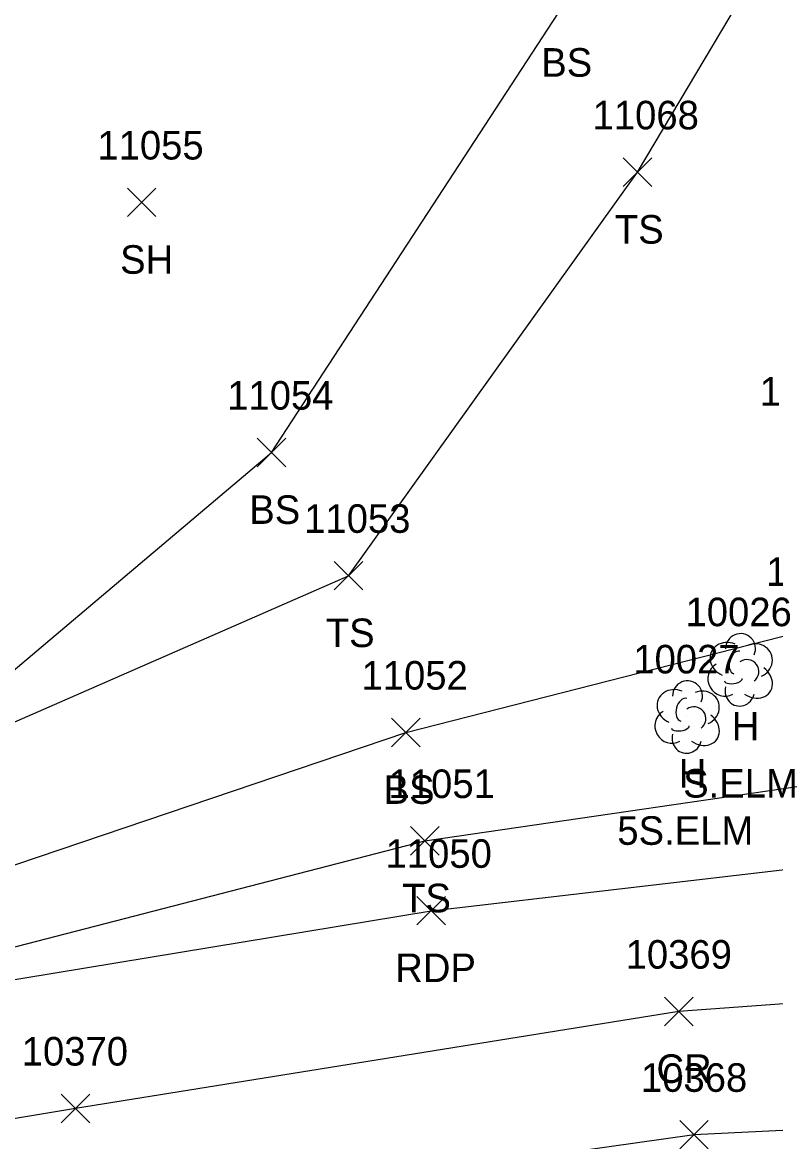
# Model space of a CAD drawing. Extents: x 1475671 to 1477951, y 592661 to 593821.
# Drawn here: x 1476688.2 to 1476740.9, y 593075.6 to 593153.9 of the extents above; entities that cross this region are included whole.
import ezdxf

# ---------------------------------------------------------------- set-up
doc = ezdxf.new("R2010")
doc.units = 0
for name, color, linetype in [('L_A', 7, 'Continuous'), ('L_C', 7, 'Continuous'), ('L_I', 7, 'Continuous'), ('L_TIC', 7, 'Continuous'), ('LELB', 7, 'Continuous'), ('LTD', 7, 'Continuous'), ('P_A', 7, 'Continuous'), ('P_I', 7, 'Continuous'), ('P_TIC', 7, 'Continuous'), ('PET', 7, 'Continuous'), ('PRC', 7, 'Continuous')]:
    doc.layers.add(name, color=color, linetype=linetype)

msp = doc.modelspace()

# ---------------------------------------------------------------- linework, layer by layer
at = {"layer": 'L_TIC'}
for points in [[(1476730.223, 593142.421), (1476732.223, 593144.421)], [(1476732.223, 593142.421), (1476730.223, 593144.421)], [(1476695.532, 593140.311), (1476697.532, 593142.311)], [(1476697.532, 593140.311), (1476695.532, 593142.311)], [(1476704.615, 593122.798), (1476706.615, 593124.798)], [(1476706.615, 593122.798), (1476704.615, 593124.798)], [(1476710.001, 593114.173), (1476712.001, 593116.173)], [(1476712.001, 593114.173), (1476710.001, 593116.173)], [(1476714.012, 593103.198), (1476716.012, 593105.198)], [(1476716.012, 593103.198), (1476714.012, 593105.198)], [(1476715.338, 593095.606), (1476717.338, 593097.606)], [(1476717.338, 593095.606), (1476715.338, 593097.606)]]:
    msp.add_lwpolyline(points, dxfattribs=at)
at = {"layer": 'LELB'}
for points in [[(1476656.284, 593095.976), (1476668.799, 593096.978), (1476674.422, 593093.252), (1476681.706, 593092.914), (1476715.012, 593104.198), (1476743.407, 593111.461), (1476771.495, 593107.276), (1476782.768, 593105.348), (1476795.281, 593099.965), (1476811.259, 593100.054), (1476809.565, 593119.113), (1476813.359, 593153.775), (1476804.907, 593159.056), (1476804.556, 593163.805), (1476803.63, 593168.615), (1476810.963, 593186.977), (1476819.408, 593209.797), (1476828.138, 593245.308), (1476843.633, 593278.61), (1476845.713, 593295.921), (1476849.309, 593306.853)], [(1476678.643, 593100.996), (1476705.615, 593123.798), (1476726.041, 593155.108), (1476737.723, 593186.361), (1476761.68, 593213.282), (1476787.873, 593223.87), (1476810.461, 593252.94), (1476833.913, 593283.757), (1476845.713, 593295.921)], [(1476678.643, 593100.996), (1476711.001, 593115.173), (1476731.223, 593143.421), (1476747.615, 593171.009), (1476767.456, 593198.639), (1476796.546, 593210.231), (1476815.094, 593241.804), (1476843.633, 593278.61)], [(1476564.119, 593090.41), (1476564.346, 593083.027), (1476564.937, 593076.683), (1476605.53, 593077.889), (1476635.384, 593080.856), (1476648.642, 593080.648), (1476656.704, 593082.361), (1476660.671, 593090.953), (1476671.661, 593086.365), (1476683.751, 593088.182), (1476716.338, 593096.606), (1476747.988, 593101.226)]]:
    msp.add_lwpolyline(points, dxfattribs=at)
at = {"layer": 'LTD'}
for p, q in [((1476738.38, 593108.636), (1476738.38, 593108.636)), ((1476738.38, 593108.636), (1476738.38, 593108.636)), ((1476734.671, 593105.33), (1476734.671, 593105.33)), ((1476734.671, 593105.33), (1476734.671, 593105.33))]:
    msp.add_line(p, q, dxfattribs=at)
for centre in [(1476738.427, 593110.07), (1476734.717, 593106.764)]:
    msp.add_arc(centre, 1.047, 335.52715, 180.95627, dxfattribs=at)
for centre, major_axis, ratio, start_param, end_param in [((1476737.588, 593109.302), (1.21, -0.512), 0.895232, 1.570796, 4.712389), ((1476739.422, 593109.219), (-1.141, -0.483), 0.949671, 1.570796, 4.712389), ((1476738.172, 593109.094), (-0.208, -0.792), 0.645439, 3.141593, 6.283185), ((1476737.297, 593107.927), (0.584, -1.042), 0.959034, 3.141593, 6.283185), ((1476738.88, 593108.469), (-0.5, 0.667), 0.989748, 3.141593, 6.283185), ((1476739.38, 593107.803), (-1.09, 0.792), 0.841452, 1.570796, 4.712389), ((1476733.879, 593105.997), (1.21, -0.512), 0.895232, 1.570796, 4.712389), ((1476738.38, 593107.136), (0.265, 1.061), 0.942809, 1.570796, 4.712389), ((1476737.922, 593107.886), (-0.625, -0.083), 0.423636, 0, 3.141593), ((1476734.462, 593105.788), (-0.208, -0.792), 0.645439, 3.141593, 6.283185), ((1476735.712, 593105.914), (-1.141, -0.483), 0.949671, 1.570796, 4.712389), ((1476735.171, 593105.164), (-0.5, 0.667), 0.989748, 3.141593, 6.283185), ((1476733.587, 593104.622), (0.584, -1.042), 0.959034, 3.141593, 6.283185), ((1476735.671, 593104.497), (-1.09, 0.792), 0.841452, 1.570796, 4.712389), ((1476734.212, 593104.58), (-0.625, -0.083), 0.423636, 0, 3.141593), ((1476734.671, 593103.83), (0.265, 1.061), 0.942809, 1.570796, 4.712389)]:
    msp.add_ellipse(centre, major_axis=major_axis, ratio=ratio, start_param=start_param, end_param=end_param, dxfattribs=at)
at = {"layer": 'P_TIC'}
for points in [[(1476715.781, 593090.72), (1476717.781, 593092.72)], [(1476717.781, 593090.72), (1476715.781, 593092.72)], [(1476733.111, 593083.661), (1476735.111, 593085.661)], [(1476735.111, 593083.661), (1476733.111, 593085.661)], [(1476690.896, 593076.875), (1476692.896, 593078.875)], [(1476692.896, 593076.875), (1476690.896, 593078.875)], [(1476734.172, 593075.036), (1476736.172, 593077.036)], [(1476736.172, 593075.036), (1476734.172, 593077.036)]]:
    msp.add_lwpolyline(points, dxfattribs=at)
at = {"layer": 'PET'}
for points in [[(1476550.122, 593088.216), (1476546.989, 593080.789), (1476546.616, 593074.303), (1476558.015, 593070.453), (1476566.603, 593070.835), (1476605.696, 593074.016), (1476651.648, 593078.887), (1476683.811, 593086.28), (1476716.781, 593091.72), (1476756.304, 593096.319), (1476786.758, 593094.615), (1476795.521, 593092.664), (1476816.876, 593085.292), (1476835.432, 593074.221), (1476828.621, 593102.019), (1476824.417, 593119.747), (1476821.585, 593140.768), (1476821.023, 593163.56), (1476821.925, 593180.441), (1476827.117, 593207.843), (1476837.471, 593243.387), (1476848.828, 593278.298), (1476858.441, 593303.191), (1476868.192, 593333.861)], [(1476876.688, 592931.371), (1476866.386, 592975.941), (1476855.424, 593012.866), (1476851.348, 593023.14), (1476844.626, 593035.784), (1476834.266, 593048.701), (1476823.419, 593058.993), (1476807.599, 593067.923), (1476802.866, 593070.053), (1476785.813, 593074.828), (1476762.309, 593077.345), (1476735.172, 593076.036), (1476692.749, 593070.032), (1476654.269, 593063.281), (1476593.38, 593051.399), (1476557.145, 593047.344), (1476521.335, 593044.375), (1476462.498, 593038.202)]]:
    msp.add_lwpolyline(points, dxfattribs=at)
at = {"layer": 'PRC'}
msp.add_lwpolyline([(1476783.703, 593084.944), (1476761.584, 593086.675), (1476734.111, 593084.661), (1476691.896, 593077.875), (1476653.536, 593071.485), (1476592.217, 593062.913), (1476555.355, 593059.5), (1476520.454, 593058.112), (1476501.288, 593059.515), (1476493.608, 593061.898)], dxfattribs=at)

# ---------------------------------------------------------------- texts
at = {"layer": 'L_A'}
for s, p in [('BS', (1476724.482, 593150.108)), ('TS', (1476729.633, 593138.421)), ('SH', (1476695.021, 593136.311)), ('BS', (1476704.056, 593118.798)), ('TS', (1476709.41, 593110.173)), ('H', (1476737.813, 593103.636)), ('H', (1476734.104, 593100.33)), ('BS', (1476713.453, 593099.198)), ('TS', (1476714.747, 593091.606))]:
    msp.add_text(s, height=2, dxfattribs=at).set_placement(p)
at = {"layer": 'L_C'}
for s, p in [('S.ELM', (1476734.412, 593099.636)), ('5S.ELM', (1476729.804, 593096.33))]:
    msp.add_text(s, height=2, dxfattribs=at).set_placement(p)
at = {"layer": 'L_I'}
for s, p in [('11068', (1476728.074, 593146.421)), ('11055', (1476693.43, 593144.311)), ('11054', (1476702.512, 593126.798)), ('11069', (1476739.759, 593127.076)), ('11053', (1476707.898, 593118.173)), ('11070', (1476740.218, 593114.461)), ('10026', (1476734.577, 593111.636)), ('10027', (1476730.923, 593108.33)), ('11052', (1476711.909, 593107.198)), ('11051', (1476713.802, 593099.606))]:
    msp.add_text(s, height=2, dxfattribs=at).set_placement(p)
at = {"layer": 'P_A'}
for s, p in [('RDP', (1476714.269, 593086.72)), ('CR', (1476732.544, 593079.661))]:
    msp.add_text(s, height=2, dxfattribs=at).set_placement(p)
at = {"layer": 'P_I'}
for s, p in [('11050', (1476713.592, 593094.72)), ('10369', (1476730.386, 593087.661)), ('10370', (1476688.14, 593080.875)), ('10368', (1476731.456, 593079.036))]:
    msp.add_text(s, height=2, dxfattribs=at).set_placement(p)

doc.saveas('drawing.dxf')
